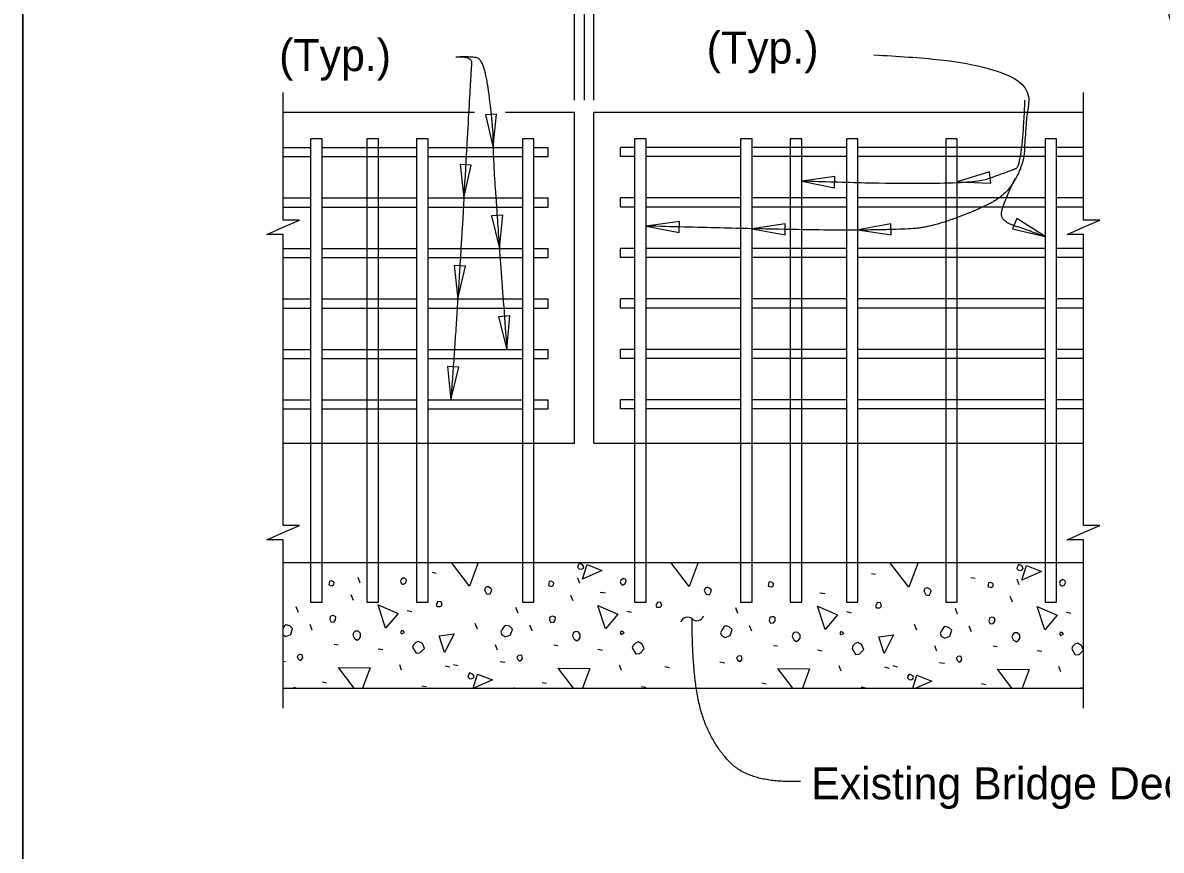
# Model space of a CAD drawing. Extents: x 0 to 41.1, y 0 to 25.9.
# Drawn here: x 0 to 7.16, y 9.64 to 14.85 of the extents above; entities that cross this region are included whole.
import ezdxf

# ---------------------------------------------------------------- set-up
doc = ezdxf.new("R2010")
doc.units = 0
for name, color, linetype in [('Dimension', 7, 'Continuous'), ('Miscellaneous', 7, 'Continuous'), ('Miscellaneous1', 7, 'Continuous'), ('Rebar', 7, 'Continuous'), ('Rebar_h', 7, 'Continuous'), ('TextStructures', 7, 'Continuous'), ('TrafBarrierConc', 7, 'Continuous')]:
    doc.layers.add(name, color=color, linetype=linetype)

msp = doc.modelspace()

# ---------------------------------------------------------------- linework, layer by layer
at = {"layer": 'Dimension'}
for p, q in [((3.4718, 14.3609), (3.4718, 15.7194)), ((3.5943, 14.3609), (3.5943, 15.7194))]:
    msp.add_line(p, q, dxfattribs=at)
for points in [[(0, 0), (41.0507, 0), (41.0507, 25.9462), (0, 25.9462)], [(2.9601, 14.0639), (2.9812, 14.2741), (2.9108, 14.2693)], [(2.7753, 13.7462), (2.8225, 13.9521), (2.7521, 13.9562)], [(5.8805, 13.8487), (6.0915, 13.8401), (6.0826, 13.9101)], [(4.9015, 13.8518), (5.1086, 13.8101), (5.1107, 13.8806)], [(2.9995, 13.4285), (3.02, 13.6387), (2.9496, 13.6337)], [(6.4326, 13.5038), (6.2542, 13.6169), (6.2269, 13.5519)], [(3.9225, 13.5695), (4.1297, 13.5286), (4.1316, 13.5991)], [(4.5888, 13.553), (4.7963, 13.5138), (4.7977, 13.5843)], [(5.2555, 13.5455), (5.4643, 13.5137), (5.4631, 13.5843)], [(2.7369, 13.1108), (2.785, 13.3165), (2.7146, 13.3209)], [(3.0461, 12.7931), (3.0638, 13.0036), (2.9935, 12.9977)], [(2.6938, 12.4754), (2.7438, 12.6806), (2.6734, 12.6856)]]:
    msp.add_lwpolyline(points, close=True, dxfattribs=at)
for points in [[(1.6385, 12.6646), (1.6385, 13.5171), (1.5352, 13.5171), (1.6385, 13.5621), (1.7419, 13.6071), (1.6385, 13.6071), (1.6385, 14.4103)], [(6.675, 12.6646), (6.675, 13.5171), (6.5716, 13.5171), (6.675, 13.5621), (6.7783, 13.6071), (6.675, 13.6071), (6.675, 14.4103)], [(1.6385, 10.5353), (1.6385, 11.5951), (1.5352, 11.5951), (1.6385, 11.6401), (1.7419, 11.6851), (1.6385, 11.6851), (1.6385, 12.6646)], [(6.675, 10.5353), (6.675, 11.5951), (6.5716, 11.5951), (6.675, 11.6401), (6.7783, 11.6851), (6.675, 11.6851), (6.675, 12.6646)]]:
    msp.add_lwpolyline(points, dxfattribs=at)
for centre, start, end in [((4.1829, 11.0625), 49.32944, 161.05666), ((4.2412, 11.1303), 229.32944, 341.05666)]:
    msp.add_arc(centre, 0.0447, start, end, dxfattribs=at)
for points in [[(6.6191, 16.4096), (6.9213, 16.403), (7.1184, 16.3767), (7.1579, 15.8706), (7.1579, 14.957), (7.3813, 14.5363), (7.5784, 14.1683), (8.1762, 13.9382)], [(2.7503, 14.6354), (2.8283, 14.6345), (2.8197, 14.548), (2.7394, 13.0971), (2.6938, 12.4754)], [(2.725, 14.6344), (2.801, 14.6387), (2.9022, 14.626), (2.9576, 14.2016), (2.9595, 14.0294), (2.9739, 13.7651), (3.046, 12.7931)], [(5.3563, 14.6472), (6.3516, 14.6056), (6.3044, 14.1195), (6.301, 13.9672), (6.1922, 13.7655), (5.9792, 13.657), (5.7054, 13.5619), (5.5308, 13.5466), (4.9527, 13.5409), (3.9224, 13.5695)], [(6.3042, 14.3612), (6.2871, 13.9449), (6.2091, 13.9146), (5.9334, 13.8156), (4.9014, 13.8518)], [(6.2447, 13.8715), (6.1674, 13.7103), (6.1474, 13.6037), (6.3323, 13.5419), (6.4325, 13.5038)], [(4.8931, 10.0739), (4.5782, 10.0603), (4.3194, 10.3295), (4.2121, 10.7215), (4.2121, 11.0964)]]:
    msp.add_open_spline(points, degree=2, dxfattribs=at)
at = {"layer": 'Miscellaneous'}
for p, q in [((3.533, 15.5314), (3.533, 14.3609)), ((2.1225, 11.3227), (2.1101, 11.3563)), ((2.5751, 11.3899), (2.6016, 11.3846)), ((3.5049, 11.3192), (3.4925, 11.3527)), ((5.3398, 11.3828), (5.3664, 11.3775)), ((5.9656, 11.358), (5.9922, 11.3527)), ((6.2697, 11.3121), (6.2573, 11.3457)), ((2.0801, 11.2131), (2.0659, 11.2484)), ((3.634, 11.2644), (3.6658, 11.2608)), ((5.0163, 11.2608), (5.0482, 11.2573)), ((3.4625, 11.2096), (3.4483, 11.2449)), ((6.2273, 11.2025), (6.2131, 11.2378)), ((1.7354, 11.1371), (1.7212, 11.1724)), ((2.4195, 11.1495), (2.4478, 11.1424)), ((3.1178, 11.1335), (3.1036, 11.1689)), ((3.8019, 11.1459), (3.8302, 11.1388)), ((4.5002, 11.13), (4.486, 11.1654)), ((5.1843, 11.1424), (5.2126, 11.1353)), ((5.8826, 11.1265), (5.8684, 11.1618)), ((6.5667, 11.1388), (6.595, 11.1318)), ((1.822, 11.0257), (1.8078, 11.0611)), ((2.8614, 11.0328), (2.8473, 11.0681)), ((3.2044, 11.0222), (3.1902, 11.0575)), ((4.5868, 11.0186), (4.5726, 11.054)), ((5.6262, 11.0257), (5.6121, 11.0611)), ((5.9692, 11.0151), (5.955, 11.0505)), ((1.9599, 10.9373), (1.9846, 10.9338)), ((2.2356, 10.909), (2.2657, 10.9037)), ((2.987, 10.9002), (2.9746, 10.9338)), ((3.3423, 10.9338), (3.367, 10.9303)), ((3.618, 10.9055), (3.6481, 10.9002)), ((4.7247, 10.9303), (4.7494, 10.9267)), ((5.0004, 10.902), (5.0305, 10.8967)), ((5.7517, 10.8931), (5.7394, 10.9267)), ((6.1071, 10.9267), (6.1318, 10.9232)), ((6.3828, 10.8984), (6.4129, 10.8931)), ((1.6385, 10.8301), (1.6523, 10.8277)), ((3.0046, 10.8295), (3.0347, 10.8242)), ((4.387, 10.826), (4.4171, 10.8206)), ((5.7694, 10.8224), (5.7995, 10.8171)), ((2.3841, 10.7747), (2.3718, 10.8083)), ((2.6581, 10.8012), (2.6864, 10.7941)), ((2.7094, 10.81), (2.7377, 10.803)), ((3.7665, 10.7712), (3.7542, 10.8047)), ((4.0405, 10.7977), (4.0688, 10.7906)), ((5.1489, 10.7676), (5.1366, 10.8012)), ((5.4229, 10.7941), (5.4512, 10.7871)), ((5.4742, 10.803), (5.5025, 10.7959)), ((6.5313, 10.7641), (6.5189, 10.7977)), ((1.8856, 10.7004), (1.9121, 10.6951)), ((2.5114, 10.6757), (2.5379, 10.6704)), ((3.268, 10.6969), (3.2945, 10.6916)), ((4.6504, 10.6934), (4.6769, 10.6881)), ((6.0328, 10.6898), (6.0593, 10.6845)), ((2.8042, 10.6603), (2.8031, 10.6633)), ((3.8938, 10.6722), (3.9203, 10.6669)), ((5.2762, 10.6686), (5.3027, 10.6633)), ((6.6586, 10.6651), (6.675, 10.6618))]:
    msp.add_line(p, q, dxfattribs=at)
for points in [[(2.8102, 11.3032), (2.6972, 11.4519)], [(2.8657, 11.4519), (2.8102, 11.3032)], [(3.5014, 11.4111), (3.5137, 11.4093), (3.5261, 11.4146), (3.5297, 11.4252), (3.5244, 11.4341), (3.5137, 11.4411), (3.5014, 11.4464), (3.4943, 11.4323), (3.4908, 11.4217), (3.5014, 11.4111)], [(3.5226, 11.3474), (3.5509, 11.4394), (3.6446, 11.4022), (3.5226, 11.3474)], [(4.1926, 11.2997), (4.0769, 11.4519)], [(4.2495, 11.4519), (4.1926, 11.2997)], [(5.575, 11.2962), (5.4566, 11.4519)], [(5.6332, 11.4519), (5.575, 11.2962)], [(6.2662, 11.404), (6.2785, 11.4022), (6.2909, 11.4075), (6.2944, 11.4182), (6.2891, 11.427), (6.2785, 11.4341), (6.2662, 11.4394), (6.2591, 11.4252), (6.2556, 11.4146), (6.2662, 11.404)], [(6.2874, 11.3404), (6.3157, 11.4323), (6.4093, 11.3952), (6.2874, 11.3404)], [(1.9263, 11.3103), (1.9457, 11.305), (1.9581, 11.3139), (1.9599, 11.3262), (1.9563, 11.3298), (1.9422, 11.3368), (1.9298, 11.3351), (1.9281, 11.3227), (1.9263, 11.3103)], [(2.3877, 11.3156), (2.3947, 11.3156), (2.4089, 11.3227), (2.4142, 11.3386), (2.4124, 11.3474), (2.3983, 11.3545), (2.3806, 11.3439), (2.3771, 11.3333), (2.3806, 11.3227), (2.3877, 11.3156)], [(3.3087, 11.3068), (3.3281, 11.3015), (3.3405, 11.3103), (3.3423, 11.3227), (3.3387, 11.3262), (3.3246, 11.3333), (3.3122, 11.3315), (3.3105, 11.3192), (3.3087, 11.3068)], [(3.7701, 11.3121), (3.7771, 11.3121), (3.7913, 11.3192), (3.7966, 11.3351), (3.7948, 11.3439), (3.7807, 11.351), (3.763, 11.3404), (3.7595, 11.3298), (3.763, 11.3192), (3.7701, 11.3121)], [(4.6911, 11.3032), (4.7105, 11.2979), (4.7229, 11.3068), (4.7247, 11.3192), (4.7211, 11.3227), (4.707, 11.3298), (4.6946, 11.328), (4.6928, 11.3156), (4.6911, 11.3032)], [(6.0735, 11.2997), (6.0929, 11.2944), (6.1053, 11.3032), (6.1071, 11.3156), (6.1035, 11.3192), (6.0894, 11.3262), (6.077, 11.3245), (6.0752, 11.3121), (6.0735, 11.2997)], [(6.5349, 11.305), (6.5419, 11.305), (6.5561, 11.3121), (6.5614, 11.328), (6.5596, 11.3368), (6.5455, 11.3439), (6.5278, 11.3333), (6.5243, 11.3227), (6.5278, 11.3121), (6.5349, 11.305)], [(2.9092, 11.2714), (2.918, 11.2555), (2.9392, 11.252), (2.9481, 11.2679), (2.9516, 11.282), (2.9428, 11.2909), (2.9268, 11.2997), (2.9109, 11.2944), (2.9056, 11.2785), (2.9092, 11.2714)], [(4.2916, 11.2679), (4.3004, 11.252), (4.3216, 11.2484), (4.3305, 11.2644), (4.334, 11.2785), (4.3251, 11.2873), (4.3092, 11.2962), (4.2933, 11.2909), (4.288, 11.275), (4.2916, 11.2679)], [(5.674, 11.2644), (5.6828, 11.2484), (5.704, 11.2449), (5.7128, 11.2608), (5.7164, 11.275), (5.7075, 11.2838), (5.6916, 11.2926), (5.6757, 11.2873), (5.6704, 11.2714), (5.674, 11.2644)], [(2.2834, 11.0381), (2.2356, 11.1848), (2.3612, 11.13), (2.2834, 11.0381)], [(2.6069, 11.1742), (2.6281, 11.1742), (2.6387, 11.1848), (2.6334, 11.2043), (2.6104, 11.206), (2.6069, 11.1954), (2.6016, 11.1866), (2.6069, 11.1742), (2.6033, 11.1777)], [(3.6658, 11.0345), (3.618, 11.1813), (3.7436, 11.1265), (3.6658, 11.0345)], [(3.9893, 11.1707), (4.0105, 11.1707), (4.0211, 11.1813), (4.0158, 11.2007), (3.9928, 11.2025), (3.9893, 11.1919), (3.984, 11.183), (3.9893, 11.1707), (3.9857, 11.1742)], [(5.0482, 11.031), (5.0004, 11.1777), (5.1259, 11.1229), (5.0482, 11.031)], [(5.3717, 11.1671), (5.3929, 11.1671), (5.4035, 11.1777), (5.3982, 11.1972), (5.3752, 11.199), (5.3717, 11.1883), (5.3664, 11.1795), (5.3717, 11.1671), (5.3681, 11.1707)], [(1.9316, 11.0929), (1.9404, 11.077), (1.9599, 11.0787), (1.9687, 11.0911), (1.9705, 11.1106), (1.9581, 11.1159), (1.9493, 11.1176), (1.9387, 11.1141), (1.9351, 11.1106), (1.9316, 11.0929)], [(3.314, 11.0893), (3.3228, 11.0734), (3.3423, 11.0752), (3.3511, 11.0876), (3.3529, 11.107), (3.3405, 11.1123), (3.3317, 11.1141), (3.3211, 11.1106), (3.3175, 11.107), (3.314, 11.0893)], [(4.6964, 11.0858), (4.7052, 11.0699), (4.7247, 11.0717), (4.7335, 11.084), (4.7353, 11.1035), (4.7229, 11.1088), (4.7141, 11.1106), (4.7035, 11.107), (4.6999, 11.1035), (4.6964, 11.0858)], [(6.0788, 11.0823), (6.0876, 11.0664), (6.1071, 11.0681), (6.1159, 11.0805), (6.1177, 11.1), (6.1053, 11.1053), (6.0965, 11.107), (6.0858, 11.1035), (6.0823, 11.1), (6.0788, 11.0823)], [(6.4306, 11.0275), (6.3828, 11.1742), (6.5083, 11.1194), (6.4306, 11.0275)], [(1.6385, 10.9961), (1.6558, 10.9868), (1.6859, 10.9992), (1.6982, 11.0363), (1.6806, 11.054), (1.6576, 11.0593), (1.647, 11.0522), (1.6385, 11.039)], [(3.0152, 10.9957), (3.0382, 10.9833), (3.0683, 10.9957), (3.0806, 11.0328), (3.063, 11.0505), (3.04, 11.0558), (3.0294, 11.0487), (3.017, 11.0292), (3.0082, 11.0133), (3.0152, 10.9957)], [(4.3976, 10.9921), (4.4206, 10.9797), (4.4507, 10.9921), (4.463, 11.0292), (4.4454, 11.0469), (4.4224, 11.0522), (4.4118, 11.0452), (4.3994, 11.0257), (4.3906, 11.0098), (4.3976, 10.9921)], [(5.78, 10.9886), (5.803, 10.9762), (5.8331, 10.9886), (5.8454, 11.0257), (5.8278, 11.0434), (5.8048, 11.0487), (5.7942, 11.0416), (5.7818, 11.0222), (5.773, 11.0063), (5.78, 10.9886)], [(2.0766, 10.9939), (2.0872, 10.9727), (2.1048, 10.9621), (2.119, 10.9727), (2.126, 10.9833), (2.126, 11.0045), (2.1101, 11.0204), (2.0907, 11.0186), (2.0819, 11.0098), (2.0766, 10.9939)], [(2.3824, 11.0027), (2.4018, 11.0116), (2.3947, 11.0186), (2.3824, 11.0239), (2.3771, 11.0116), (2.3824, 11.0027)], [(2.6546, 10.8861), (2.621, 10.9904), (2.7147, 11.0027), (2.6546, 10.8861)], [(3.4589, 10.9904), (3.4696, 10.9691), (3.4872, 10.9585), (3.5014, 10.9691), (3.5084, 10.9797), (3.5084, 11.001), (3.4925, 11.0169), (3.4731, 11.0151), (3.4642, 11.0063), (3.4589, 10.9904)], [(3.7648, 10.9992), (3.7842, 11.008), (3.7771, 11.0151), (3.7648, 11.0204), (3.7595, 11.008), (3.7648, 10.9992)], [(4.8413, 10.9868), (4.8519, 10.9656), (4.8696, 10.955), (4.8838, 10.9656), (4.8908, 10.9762), (4.8908, 10.9974), (4.8749, 11.0133), (4.8555, 11.0116), (4.8466, 11.0027), (4.8413, 10.9868)], [(5.1472, 10.9957), (5.1666, 11.0045), (5.1595, 11.0116), (5.1472, 11.0169), (5.1419, 11.0045), (5.1472, 10.9957)], [(5.4194, 10.879), (5.3858, 10.9833), (5.4795, 10.9957), (5.4194, 10.879)], [(6.2237, 10.9833), (6.2343, 10.9621), (6.252, 10.9515), (6.2662, 10.9621), (6.2732, 10.9727), (6.2732, 10.9939), (6.2573, 11.0098), (6.2379, 11.008), (6.229, 10.9992), (6.2237, 10.9833)], [(6.5296, 10.9921), (6.549, 11.001), (6.5419, 11.008), (6.5296, 11.0133), (6.5243, 11.001), (6.5296, 10.9921)], [(2.4531, 10.9179), (2.4761, 10.8808), (2.499, 10.8825), (2.5079, 10.8914), (2.5273, 10.9108), (2.515, 10.9409), (2.4902, 10.955), (2.4725, 10.9479), (2.4584, 10.9338), (2.4531, 10.9179)], [(3.8355, 10.9143), (3.8585, 10.8772), (3.8814, 10.879), (3.8903, 10.8878), (3.9097, 10.9073), (3.8974, 10.9373), (3.8726, 10.9515), (3.8549, 10.9444), (3.8408, 10.9303), (3.8355, 10.9143)], [(5.2179, 10.9108), (5.2409, 10.8737), (5.2638, 10.8754), (5.2727, 10.8843), (5.2921, 10.9037), (5.2797, 10.9338), (5.255, 10.9479), (5.2373, 10.9409), (5.2232, 10.9267), (5.2179, 10.9108)], [(6.6003, 10.9073), (6.6232, 10.8701), (6.6462, 10.8719), (6.6551, 10.8808), (6.6745, 10.9002), (6.6621, 10.9303), (6.6374, 10.9444), (6.6197, 10.9373), (6.6056, 10.9232), (6.6003, 10.9073)], [(1.7336, 10.8454), (1.7442, 10.8348), (1.7548, 10.8419), (1.7619, 10.8525), (1.7584, 10.8701), (1.7495, 10.8719), (1.7371, 10.8701), (1.7265, 10.8595), (1.7336, 10.8454)], [(3.116, 10.8419), (3.1266, 10.8313), (3.1372, 10.8383), (3.1443, 10.8489), (3.1407, 10.8666), (3.1319, 10.8684), (3.1195, 10.8666), (3.1089, 10.856), (3.116, 10.8419)], [(4.4984, 10.8383), (4.509, 10.8277), (4.5196, 10.8348), (4.5267, 10.8454), (4.5231, 10.8631), (4.5143, 10.8648), (4.5019, 10.8631), (4.4913, 10.8525), (4.4984, 10.8383)], [(5.8808, 10.8348), (5.8914, 10.8242), (5.902, 10.8313), (5.9091, 10.8419), (5.9055, 10.8595), (5.8967, 10.8613), (5.8843, 10.8595), (5.8737, 10.8489), (5.8808, 10.8348)], [(2.0854, 10.6603), (1.9864, 10.7906), (2.1862, 10.7888), (2.1381, 10.6603)], [(2.8119, 10.7217), (2.8243, 10.7199), (2.8367, 10.7252), (2.8402, 10.7358), (2.8349, 10.7446), (2.8243, 10.7517), (2.8119, 10.757), (2.8049, 10.7429), (2.8013, 10.7323), (2.8119, 10.7217)], [(2.8339, 10.6603), (2.8614, 10.7499), (2.9551, 10.7128), (2.8382, 10.6603)], [(3.4651, 10.6603), (3.3688, 10.7871), (3.5685, 10.7853), (3.5218, 10.6603)], [(4.8449, 10.6603), (4.7512, 10.7835), (4.9509, 10.7818), (4.9055, 10.6603)], [(5.5767, 10.7146), (5.5891, 10.7128), (5.6015, 10.7181), (5.605, 10.7287), (5.5997, 10.7376), (5.5891, 10.7446), (5.5767, 10.7499), (5.5697, 10.7358), (5.5661, 10.7252), (5.5767, 10.7146)], [(6.2246, 10.6603), (6.1336, 10.78), (6.3333, 10.7782), (6.2893, 10.6603)], [(5.6008, 10.6603), (5.6262, 10.7429), (5.7199, 10.7057), (5.6187, 10.6603)], [(1.7185, 10.6603), (1.7089, 10.6651), (1.7008, 10.6603)], [(3.0938, 10.6603), (3.0912, 10.6615), (3.0891, 10.6603)]]:
    msp.add_lwpolyline(points, dxfattribs=at)
at = {"layer": 'Miscellaneous1'}
msp.add_lwpolyline([(0, 25.9462), (41.0507, 25.9462), (41.0507, 0), (0, 0)], close=True, dxfattribs=at)
at = {"layer": 'Rebar'}
for p, q in [((1.6385, 14.0639), (1.8105, 14.0639)), ((1.8835, 14.0639), (2.4772, 14.0639)), ((2.5501, 14.0639), (3.1435, 14.0639)), ((3.2165, 14.0639), (3.3051, 14.0639)), ((3.3051, 14.0066), (3.3051, 14.0639)), ((3.7609, 14.0066), (3.7609, 14.0639)), ((3.8495, 14.0639), (3.7609, 14.0639)), ((4.5158, 14.0639), (3.9224, 14.0639)), ((5.1825, 14.0639), (4.5887, 14.0639)), ((6.4325, 14.0639), (5.2554, 14.0639)), ((6.675, 14.0639), (6.5054, 14.0639)), ((1.6385, 14.0066), (1.8105, 14.0066)), ((1.8835, 14.0066), (2.4772, 14.0066)), ((2.5501, 14.0066), (3.1435, 14.0066)), ((3.2165, 14.0066), (3.3051, 14.0066)), ((3.8495, 14.0066), (3.7609, 14.0066)), ((4.5158, 14.0066), (3.9224, 14.0066)), ((5.1825, 14.0066), (4.5887, 14.0066)), ((6.4325, 14.0066), (5.2554, 14.0066)), ((6.675, 14.0066), (6.5054, 14.0066)), ((1.6385, 13.7462), (1.8105, 13.7462)), ((1.6385, 13.6889), (1.8105, 13.6889)), ((1.8835, 13.7462), (2.4772, 13.7462)), ((1.8835, 13.6889), (2.4772, 13.6889)), ((2.5501, 13.7462), (3.1435, 13.7462)), ((2.5501, 13.6889), (3.1435, 13.6889)), ((3.2165, 13.7462), (3.3051, 13.7462)), ((3.2165, 13.6889), (3.3051, 13.6889)), ((3.3051, 13.6889), (3.3051, 13.7462)), ((3.7609, 13.6889), (3.7609, 13.7462)), ((3.8495, 13.7462), (3.7609, 13.7462)), ((3.8495, 13.6889), (3.7609, 13.6889)), ((4.5158, 13.7462), (3.9224, 13.7462)), ((4.5158, 13.6889), (3.9224, 13.6889)), ((5.1825, 13.7462), (4.5887, 13.7462)), ((5.1825, 13.6889), (4.5887, 13.6889)), ((6.4325, 13.7462), (5.2554, 13.7462)), ((6.4325, 13.6889), (5.2554, 13.6889)), ((6.675, 13.7462), (6.5054, 13.7462)), ((6.675, 13.6889), (6.5054, 13.6889)), ((1.6385, 13.4285), (1.8105, 13.4285)), ((1.8835, 13.4285), (2.4772, 13.4285)), ((2.5501, 13.4285), (3.1435, 13.4285)), ((3.2165, 13.4285), (3.3051, 13.4285)), ((3.3051, 13.3712), (3.3051, 13.4285)), ((3.7609, 13.3712), (3.7609, 13.4285)), ((3.8495, 13.4285), (3.7609, 13.4285)), ((4.5158, 13.4285), (3.9224, 13.4285)), ((5.1825, 13.4285), (4.5887, 13.4285)), ((6.4325, 13.4285), (5.2554, 13.4285)), ((6.675, 13.4285), (6.5054, 13.4285)), ((1.6385, 13.3712), (1.8105, 13.3712)), ((1.8835, 13.3712), (2.4772, 13.3712)), ((2.5501, 13.3712), (3.1435, 13.3712)), ((3.2165, 13.3712), (3.3051, 13.3712)), ((3.8495, 13.3712), (3.7609, 13.3712)), ((4.5158, 13.3712), (3.9224, 13.3712)), ((5.1825, 13.3712), (4.5887, 13.3712)), ((6.4325, 13.3712), (5.2554, 13.3712)), ((6.675, 13.3712), (6.5054, 13.3712)), ((1.6385, 13.1108), (1.8105, 13.1108)), ((1.8835, 13.1108), (2.4772, 13.1108)), ((2.5501, 13.1108), (3.1435, 13.1108)), ((3.2165, 13.1108), (3.3051, 13.1108)), ((3.3051, 13.0535), (3.3051, 13.1108)), ((3.7609, 13.0535), (3.7609, 13.1108)), ((3.8495, 13.1108), (3.7609, 13.1108)), ((4.5158, 13.1108), (3.9224, 13.1108)), ((5.1825, 13.1108), (4.5887, 13.1108)), ((6.4325, 13.1108), (5.2554, 13.1108)), ((6.675, 13.1108), (6.5054, 13.1108)), ((1.6385, 13.0535), (1.8105, 13.0535)), ((1.8835, 13.0535), (2.4772, 13.0535)), ((2.5501, 13.0535), (3.1435, 13.0535)), ((3.2165, 13.0535), (3.3051, 13.0535)), ((3.8495, 13.0535), (3.7609, 13.0535)), ((4.5158, 13.0535), (3.9224, 13.0535)), ((5.1825, 13.0535), (4.5887, 13.0535)), ((6.4325, 13.0535), (5.2554, 13.0535)), ((6.675, 13.0535), (6.5054, 13.0535)), ((1.6385, 12.7931), (1.8105, 12.7931)), ((1.8835, 12.7931), (2.4772, 12.7931)), ((2.5501, 12.7931), (3.1435, 12.7931)), ((3.2165, 12.7931), (3.3051, 12.7931)), ((3.3051, 12.7358), (3.3051, 12.7931)), ((3.7609, 12.7358), (3.7609, 12.7931)), ((3.8495, 12.7931), (3.7609, 12.7931)), ((4.5158, 12.7931), (3.9224, 12.7931)), ((5.1825, 12.7931), (4.5887, 12.7931)), ((6.4325, 12.7931), (5.2554, 12.7931)), ((6.675, 12.7931), (6.5054, 12.7931)), ((1.6385, 12.7358), (1.8105, 12.7358)), ((1.8835, 12.7358), (2.4772, 12.7358)), ((2.5501, 12.7358), (3.1435, 12.7358)), ((3.2165, 12.7358), (3.3051, 12.7358)), ((3.8495, 12.7358), (3.7609, 12.7358)), ((4.5158, 12.7358), (3.9224, 12.7358)), ((5.1825, 12.7358), (4.5887, 12.7358)), ((6.4325, 12.7358), (5.2554, 12.7358)), ((6.675, 12.7358), (6.5054, 12.7358)), ((1.6385, 12.4754), (1.8105, 12.4754)), ((1.8835, 12.4754), (2.4772, 12.4754)), ((2.5501, 12.4754), (3.1435, 12.4754)), ((3.2165, 12.4754), (3.3051, 12.4754)), ((3.3051, 12.4181), (3.3051, 12.4754)), ((3.7609, 12.4181), (3.7609, 12.4754)), ((3.8495, 12.4754), (3.7609, 12.4754)), ((4.5158, 12.4754), (3.9224, 12.4754)), ((5.1825, 12.4754), (4.5887, 12.4754)), ((6.4325, 12.4754), (5.2554, 12.4754)), ((6.675, 12.4754), (6.5054, 12.4754)), ((1.6385, 12.4181), (1.8105, 12.4181)), ((1.8835, 12.4181), (2.4772, 12.4181)), ((2.5501, 12.4181), (3.1435, 12.4181)), ((3.2165, 12.4181), (3.3051, 12.4181)), ((3.8495, 12.4181), (3.7609, 12.4181)), ((4.5158, 12.4181), (3.9224, 12.4181)), ((5.1825, 12.4181), (4.5887, 12.4181)), ((6.4325, 12.4181), (5.2554, 12.4181)), ((6.675, 12.4181), (6.5054, 12.4181))]:
    msp.add_line(p, q, dxfattribs=at)
for points in [[(1.8835, 14.1186), (1.8105, 14.1186), (1.8105, 11.2019), (1.8835, 11.2019)], [(2.5501, 14.1186), (2.4772, 14.1186), (2.4772, 11.2019), (2.5501, 11.2019)], [(3.2165, 14.1186), (3.1435, 14.1186), (3.1435, 11.2019), (3.2165, 11.2019)], [(3.9224, 14.1186), (3.8495, 14.1186), (3.8495, 11.2019), (3.9224, 11.2019)], [(4.5887, 14.1186), (4.5158, 14.1186), (4.5158, 11.2019), (4.5887, 11.2019)], [(5.2554, 14.1186), (5.1825, 14.1186), (5.1825, 11.2019), (5.2554, 11.2019)], [(6.5054, 14.1186), (6.4325, 14.1186), (6.4325, 11.2019), (6.5054, 11.2019)]]:
    msp.add_lwpolyline(points, close=True, dxfattribs=at)
at = {"layer": 'Rebar_h'}
for points in [[(2.2375, 14.1186), (2.1645, 14.1186), (2.1645, 11.2019), (2.2375, 11.2019)], [(4.9014, 14.1186), (4.8285, 14.1186), (4.8285, 11.2019), (4.9014, 11.2019)], [(5.8804, 14.1186), (5.8075, 14.1186), (5.8075, 11.2019), (5.8804, 11.2019)]]:
    msp.add_lwpolyline(points, close=True, dxfattribs=at)
at = {"layer": 'TrafBarrierConc'}
for p, q in [((1.6385, 14.2853), (2.8435, 14.2853)), ((3.0375, 14.2853), (3.4717, 14.2853)), ((3.4718, 12.2019), (3.4718, 14.2852)), ((3.5942, 14.2853), (6.675, 14.2853)), ((3.5943, 12.2019), (3.5943, 14.2852)), ((1.6385, 12.2019), (3.4717, 12.2019)), ((3.5942, 12.2019), (6.675, 12.2019)), ((1.6385, 11.4519), (6.675, 11.4519)), ((1.6385, 10.6603), (6.675, 10.6603))]:
    msp.add_line(p, q, dxfattribs=at)

# ---------------------------------------------------------------- texts
at = {"layer": 'Dimension'}
for p in [(4.3035, 14.5919), (1.6133, 14.5448)]:
    msp.add_text('(Typ.)', height=0.2016, dxfattribs=at).set_placement(p)
at = {"layer": 'TextStructures'}
msp.add_text('Existing Bridge Deck', height=0.2016, dxfattribs=at).set_placement((4.961, 9.9609))

doc.saveas('drawing.dxf')
